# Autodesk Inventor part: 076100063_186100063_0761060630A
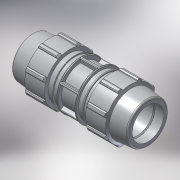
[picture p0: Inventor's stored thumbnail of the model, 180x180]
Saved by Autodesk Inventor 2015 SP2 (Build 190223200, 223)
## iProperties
Created: 2017-02
Part Number: 076100063_186100063_0761060630A
Material: PVC-Piping
Description: PLASSON REPAIR COUPLER 63
Document SubType Name: Modeling
Designer: KIM
Mass: 8658.36 g
Surface Area: 5623.3 cm^2
Volume: 6184.54 cm^3
Density: 1.4 g/cm^3
Appearance: Smooth - White
Author: KIM
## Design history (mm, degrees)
derived "07610.ipt"
feature "Solid1::07610.ipt"
tag "TaggingFeature1"
body "Solid1"
other parameters: "d2" = 63, "d4" = 22.5, "d5" = 38.57143, "d7" = 113, "d8" = 84.75, "d9" = 38.57143, "d11" = 3.48571, "d12" = 90.4, "d13" = 120 deg, "d14" = 88.2, "d15" = 6 deg, "d16" = 101.7, "d18" = 3.15, "d19" = 35 deg, "d20" = 17.5 deg, "d21" = 105.09, "d23" = 0, "d25" = 360 deg, "d27" = 2.26, "d33" = 1.26, "d34" = 5.65, "d36" = 0, "d37" = 1.26, "d38" = 1.26, "d40" = 360 deg, "d42" = 48.6, "d43" = 3.39, "d46" = 1.89, "d50" = 10.6, "d51" = 90.4, "d_" = 63, "E_" = 113, "d49" = 24.68571
